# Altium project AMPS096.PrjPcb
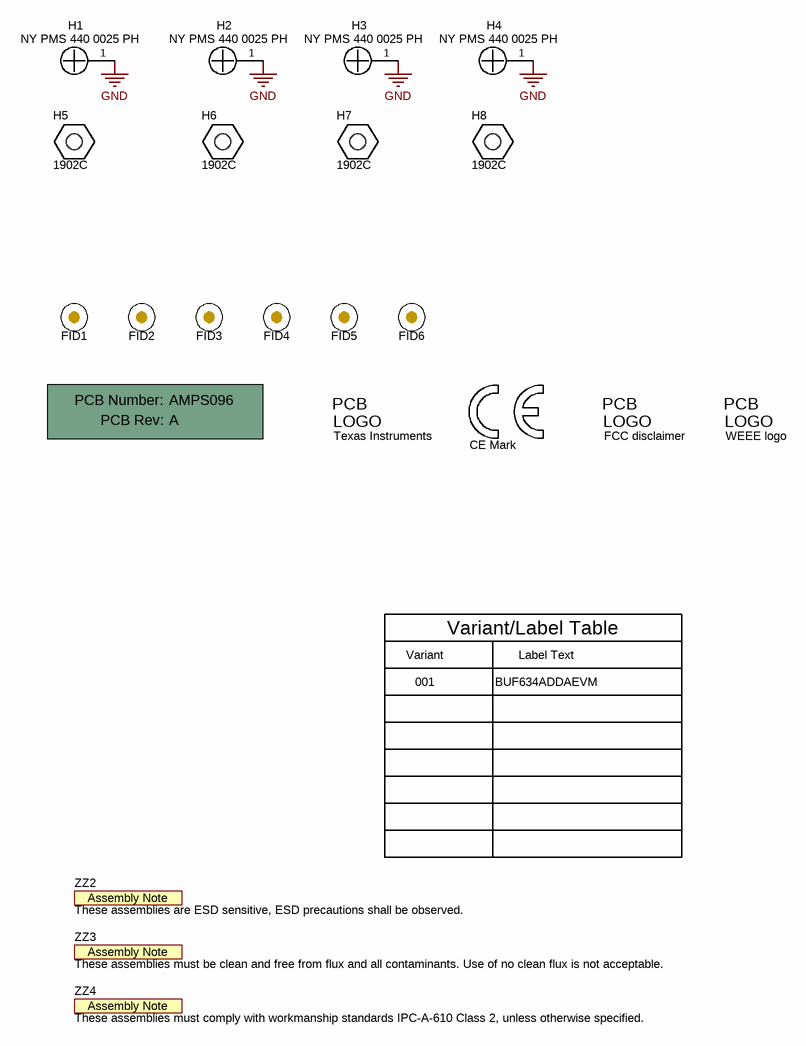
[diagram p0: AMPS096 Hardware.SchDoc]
TID: N/A; TechSupport: http://www.ti.com/support; SCH_Rev: A; Project Lead: Jacob Freet; PRJ_Title: BUF634ADDAEVM; PRJ_Number: AMPS096; PRJ_Engineer: Jacob Freet; PRJ_Customer: Public Release; PCB_Rev: A; PCB_Layout: Dennis Goeke; CopyrightYear: 2018
2 sheets, 83 parts. Net scope: global (net labels, ports and power ports of the same name join across sheets).
Board file: AMPS096.PcbDoc
Sheets:
  AMPS096 Hardware.SchDoc
  AMPS096.SchDoc

## Sheet AMPS096 Hardware.SchDoc
size 431 x 279 mm; Date: Not shown in title block; ApprovedBy: Not shown in title block; CheckedBy: Not shown in title block; Author: Not shown in title block; CompanyName: Not shown in title block; Engineer: Not shown in title block; Organization: Not shown in title block; Address1: Not shown in title block; Address2: Not shown in title block; Address3: Not shown in title block; Address4: Not shown in title block; DocumentNumber: 2; Revision: Use project parameter SCH_Rev; SheetNumber: 2; SheetTotal: 2; PageSetup: Record=PageOptions¦CenterHorizontal=True¦CenterVertical=True¦PrintScale=1.00¦XCorrection=1.00¦YCorrection=1.00¦PrintKind=0¦BorderSize=5000000¦LeftOffset=0¦BottomOffset=0¦Orientation=2¦PaperLength=1000¦PaperWidth=1000¦Scale=100¦PaperSource=15¦PrintQuality=600¦MediaType=1¦DitherType=10¦PaperKind=Letter¦PrintScaleMode=1

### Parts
!PCB  Printed Circuit Board  (value not drawn)  (mechanical)
FID1  Fiducial  [Fiducial10-20]  (value not drawn)
FID2  Fiducial  [Fiducial10-20]  (value not drawn)
FID3  Fiducial  [Fiducial10-20]  (value not drawn)
FID4  Fiducial  [Fiducial10-20]  (value not drawn)
FID5  Fiducial  [Fiducial10-20]  (value not drawn)
FID6  Fiducial  [Fiducial10-20]  (value not drawn)
H1  NY PMS 440 0025 PH  [NY PMS 440 0025 PH]
H2  NY PMS 440 0025 PH  [NY PMS 440 0025 PH]
H3  NY PMS 440 0025 PH  [NY PMS 440 0025 PH]
H4  NY PMS 440 0025 PH  [NY PMS 440 0025 PH]
H5  1902C  [Keystone_1902C]
H6  1902C  [Keystone_1902C]
H7  1902C  [Keystone_1902C]
H8  1902C  [Keystone_1902C]
Logo1  Texas Instruments  [TI_Stacked_Overlay_Small]  (no BOM)
Logo2  CE Mark  [CE_Mark_5mm]  (no BOM)
Logo3  FCC disclaimer  [FCC_disclaimer]  (no BOM)
Logo4  WEEE logo  [WEEE_Minimum]  (no BOM)
ZZ2  These assemblies are ESD sensitive, ESD precautions shall be observed.  [AssemblyNote]  (no BOM)
ZZ3  These assemblies must be clean and free from flux and all contaminants. Use of no clean flux is not acceptable.  [AssemblyNote]  (no BOM)
ZZ4  These assemblies must comply with workmanship standards IPC-A-610 Class 2, unless otherwise specified.  [AssemblyNote]  (no BOM)

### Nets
GND: H1.1 H2.1 H3.1 H4.1

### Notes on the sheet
- Variant
- Variant/Label Table
- Label Text
- 001
- BUF634ADDAEVM

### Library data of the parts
!PCB = CMP-0003618-2: Manufacturer: Any; PartNumber: AMPS096; CompType: PCB
FID1-FID6 = CMP-0077181-1: Fiducial mark.  There is nothing to buy or mount.
H1-H4 = CMP-0003617-1: Machine Screw, Round, #4-40 x 1/4, Nylon, Philips panhead; Manufacturer: B&F Fastener Supply; CompType: Hardware
H5-H8 = CMP-0003610-1: Standoff, Hex, 0.5"L #4-40 Nylon; Manufacturer: Keystone; CompType: Hardware
Logo1 = CMP-0074838-1: Texas Instrument Corporate Signature; SymbolCreator: a0412235; Lib Reference: TI_Logo; Library Reference: Logo
Logo2 = CMP-0074844-1: SymbolCreator: a0412235
Logo3 = CMP-0074847-1: FCC_disclaimer; Library Reference: Logo
Logo4 = CMP-0074769-1
ZZ2 = CMP-0077236-1
ZZ3 = CMP-0077237-1
ZZ4 = CMP-0077238-1

## Sheet AMPS096.SchDoc: BUF634ADDAEVM SCH
size 431 x 279 mm; Date: Not shown in title block; ApprovedBy: Not shown in title block; CheckedBy: Not shown in title block; Author: Not shown in title block; CompanyName: Not shown in title block; DrawnBy: Dennis Goeke; Engineer: Not shown in title block; Organization: Not shown in title block; Address1: Not shown in title block; Address2: Not shown in title block; Address3: Not shown in title block; Address4: Not shown in title block; DocumentNumber: 1; Revision: Use project parameter SCH_Rev; SheetNumber: 1; SheetTotal: 2; PageSetup: Record=PageOptions¦CenterHorizontal=True¦CenterVertical=True¦PrintScale=1.00¦XCorrection=1.00¦YCorrection=1.00¦PrintKind=0¦BorderSize=5000000¦LeftOffset=0¦BottomOffset=0¦Orientation=2¦PaperLength=1000¦PaperWidth=1000¦Scale=100¦PaperSource=15¦PrintQuality=600¦MediaType=1¦DitherType=10¦PaperKind=Letter¦PrintScaleMode=1
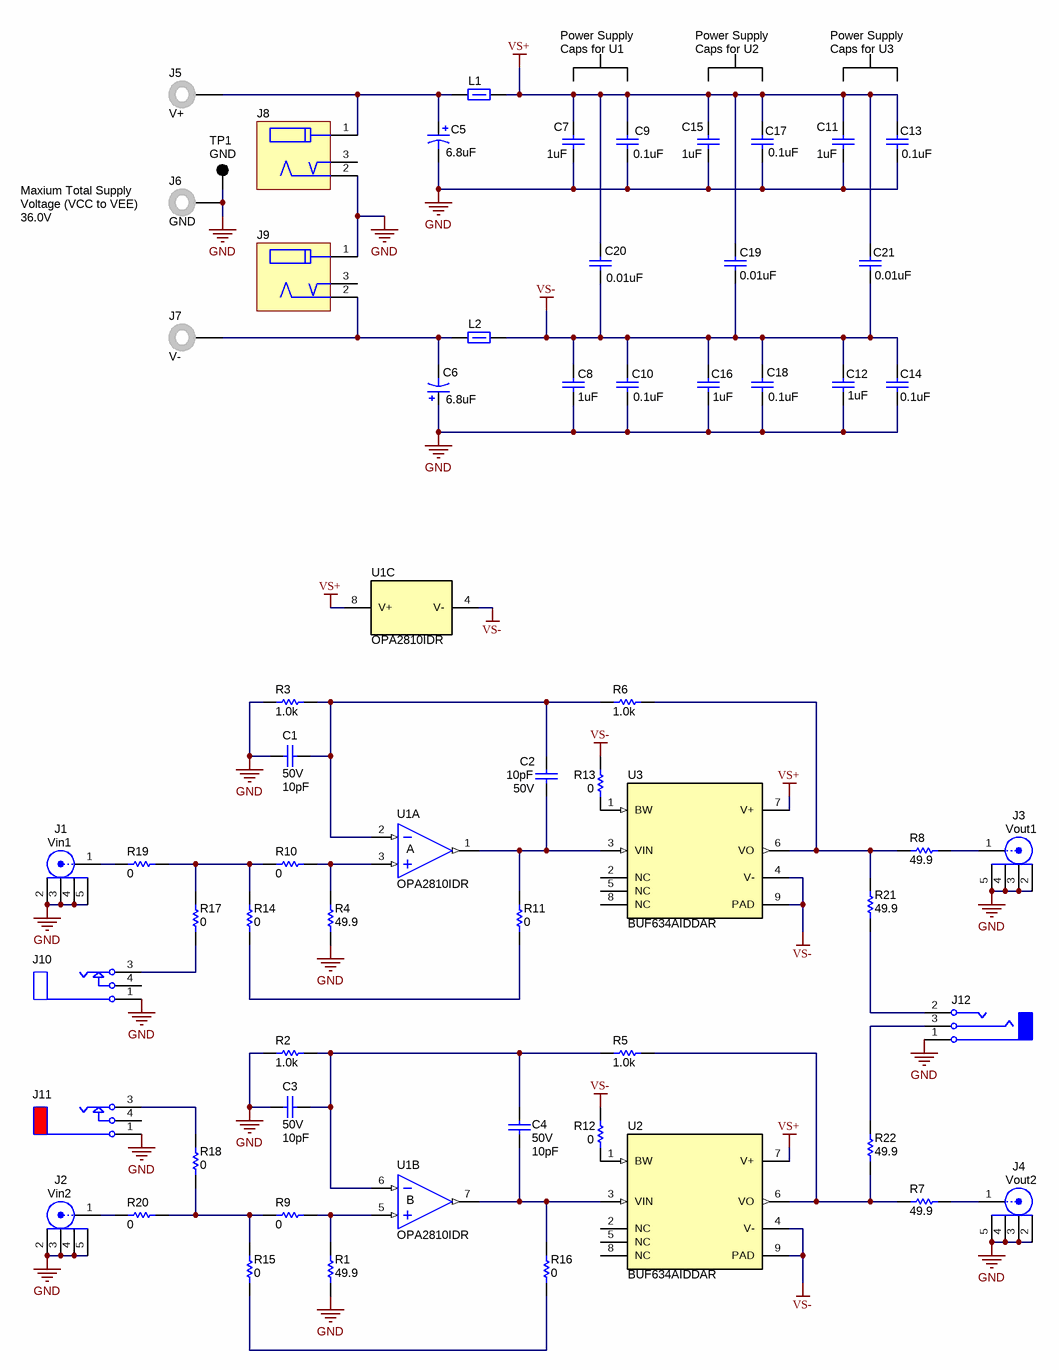
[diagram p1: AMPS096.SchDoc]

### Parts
C1  VDC_V: 50V  ValueDisplayed: 10pF  [0603L]  (hidden comment: C0603C100F5GAC7867)
C2  VDC_V: 50V  ValueDisplayed: 10pF  [0603L]  (hidden comment: C0603C100F5GAC7867)
C3  VDC_V: 50V  ValueDisplayed: 10pF  [0603L]  (hidden comment: C0603C100F5GAC7867)
C4  VDC_V: 50V  ValueDisplayed: 10pF  [0603L]  (hidden comment: C0603C100F5GAC7867)
C5  ValueDisplayed: 6.8uF  [7343-31]  (hidden comment: T495D685K050ATE300)
C6  ValueDisplayed: 6.8uF  [7343-31]  (hidden comment: T495D685K050ATE300)
C7  ValueDisplayed: 1uF  [0805L]  (hidden comment: 08055C105KAT2A)
C8  ValueDisplayed: 1uF  [0805L]  (hidden comment: 08055C105KAT2A)
C9  ValueDisplayed: 0.1uF  [0603]  (hidden comment: C1608X5R1H104K080AA)
C10  ValueDisplayed: 0.1uF  [0603]  (hidden comment: C1608X5R1H104K080AA)
C11  ValueDisplayed: 1uF  [0805L]  (hidden comment: 08055C105KAT2A)
C12  ValueDisplayed: 1uF  [0805L]  (hidden comment: 08055C105KAT2A)
C13  ValueDisplayed: 0.1uF  [0603]  (hidden comment: C1608X5R1H104K080AA)
C14  ValueDisplayed: 0.1uF  [0603]  (hidden comment: C1608X5R1H104K080AA)
C15  ValueDisplayed: 1uF  [0805L]  (hidden comment: 08055C105KAT2A)
C16  ValueDisplayed: 1uF  [0805L]  (hidden comment: 08055C105KAT2A)
C17  ValueDisplayed: 0.1uF  [0603]  (hidden comment: C1608X5R1H104K080AA)
C18  ValueDisplayed: 0.1uF  [0603]  (hidden comment: C1608X5R1H104K080AA)
C19  ValueDisplayed: 0.01uF  [0603L]  (hidden comment: 06031C103KAT2A)
C20  ValueDisplayed: 0.01uF  [0603L]  (hidden comment: 06031C103KAT2A)
C21  ValueDisplayed: 0.01uF  [0603L]  (hidden comment: 06031C103KAT2A)
J1  Vin1  [Johnson_142-0701-801_NoVias]
J2  Vin2  [Johnson_142-0701-801_NoVias]
J3  Vout1  [Johnson_142-0701-801_NoVias]
J4  Vout2  [Johnson_142-0701-801_NoVias]
J5  V+  [Keystone_6095]
J6  GND  [Keystone_6095]
J7  V-  [Keystone_6095]
J8  EJ508A  [Memory_EJ508A]  (value not drawn)
J9  EJ508A  [Memory_EJ508A]  (value not drawn)
J10  970  [Keystone_970]  (value not drawn)
J11  971  [Keystone_971]  (value not drawn)
J12  SJ-3523-SMT  [CUI_SJ-3523-SMT]  (value not drawn)
L1  HI1206N800R-10  [1206]  (value not drawn)
L2  HI1206N800R-10  [1206]  (value not drawn)
R1  ValueDisplayed: 49.9  [0603L]  (hidden comment: CRCW060349R9FKEA)
R2  ValueDisplayed: 1.0k  [0603L]  (hidden comment: CRCW06031K00JNEA)
R3  ValueDisplayed: 1.0k  [0603L]  (hidden comment: CRCW06031K00JNEA)
R4  ValueDisplayed: 49.9  [0603L]  (hidden comment: CRCW060349R9FKEA)
R5  ValueDisplayed: 1.0k  [0603L]  (hidden comment: CRCW06031K00JNEA)
R6  ValueDisplayed: 1.0k  [0603L]  (hidden comment: CRCW06031K00JNEA)
R7  ValueDisplayed: 49.9  [0603L]  (hidden comment: CRCW060349R9FKEA)
R8  ValueDisplayed: 49.9  [0603L]  (hidden comment: CRCW060349R9FKEA)
R9  ValueDisplayed: 0  [0603L]  (hidden comment: CRCW06030000Z0EA)
R10  ValueDisplayed: 0  [0603L]  (hidden comment: CRCW06030000Z0EA)
R11  ValueDisplayed: 0  [0603L]  (hidden comment: CRCW06030000Z0EA)
R12  ValueDisplayed: 0  [0603L]  (hidden comment: CRCW06030000Z0EA)
R13  ValueDisplayed: 0  [0603L]  (hidden comment: CRCW06030000Z0EA)
R14  ValueDisplayed: 0  [0603L]  (hidden comment: CRCW06030000Z0EA)
R15  ValueDisplayed: 0  [0603L]  (hidden comment: CRCW06030000Z0EA)
R16  ValueDisplayed: 0  [0603L]  (hidden comment: CRCW06030000Z0EA)
R17  ValueDisplayed: 0  [0603L]  (hidden comment: CRCW06030000Z0EA)
R18  ValueDisplayed: 0  [0603L]  (hidden comment: CRCW06030000Z0EA)
R19  ValueDisplayed: 0  [0603L]  (hidden comment: CRCW06030000Z0EA)
R20  ValueDisplayed: 0  [0603L]  (hidden comment: CRCW06030000Z0EA)
R21  ValueDisplayed: 49.9  [0603L]  (hidden comment: CRCW060349R9FKEA)
R22  ValueDisplayed: 49.9  [0603L]  (hidden comment: CRCW060349R9FKEA)
TP1  GND  [Keystone5001]
U1  OPA2810IDR  [D0008A_N]  (parts A,B,C of 3)
U2  BUF634AIDDAR  [DDA0008B_N]
U3  BUF634AIDDAR  [DDA0008B_N]

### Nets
GND: C1.2 C3.2 C5.2(-) C6.1(+) C7.2 C8.2 C9.2 C10.2 C11.2 C12.2 C13.2 C14.2 C15.2 C16.2 C17.2 C18.2 J1.2 J1.3 J1.4 J1.5 J2.2 J2.3 J2.4 J2.5 J3.2 J3.3 J3.4 J3.5 J4.2 J4.3 J4.4 J4.5 J6.1 J8.2 J9.1 J10.1(SLEEVE) J11.1(SLEEVE) J12.1(SLEEVE) R1.1 R2.1 R3.1 R4.2 TP1.1
VS+: C7.1 C9.1 C11.1 C13.1 C15.1 C17.1 C19.1 C20.1 C21.1 L1.2 U1.8(V+) U2.7(V+) U3.7(V+)
VS-: C8.1 C10.1 C12.1 C14.1 C16.1 C18.1 C19.2 C20.2 C21.2 L2.2 R12.1 R13.1 U1.4(V-) U2.4(V-) U2.9(PAD) U3.4(V-) U3.9(PAD)
NetC1_1: C1.1 C2.1 R3.2 R6.1 U1.2(IN-)
NetC2_2: C2.2 R11.2 U1.1(OUT) U3.3(VIN)
NetC3_1: C3.1 C4.1 R2.2 R5.1 U1.6(IN-)
NetC4_2: C4.2 R16.2 U1.7(OUT) U2.3(VIN)
NetC5_1: C5.1(+) J5.1 J8.1 L1.1
NetC6_2: C6.2(-) J7.1 J9.2 L2.1
NetJ1_1: J1.1 R19.2
NetJ2_1: J2.1 R20.2
NetJ3_1: J3.1 R8.1
NetJ4_1: J4.1 R7.1
NetJ10_3: J10.3(TIP) R17.1
NetJ11_3: J11.3(TIP) R18.2
NetJ12_2: J12.2(TIP) R21.2
NetJ12_3: J12.3(RING) R22.1
NetR1_2: R1.2 R9.1 U1.5(IN+)
NetR4_1: R4.1 R10.1 U1.3(IN+)
NetR5_2: R5.2 R7.2 R22.2 U2.6(VO)
NetR6_2: R6.2 R8.2 R21.1 U3.6(VO)
NetR9_2: R9.2 R15.2 R18.1 R20.1
NetR10_2: R10.2 R14.2 R17.2 R19.1
NetR11_1: R11.1 R14.1
NetR12_2: R12.2 U2.1(BW)
NetR13_2: R13.2 U3.1(BW)
NetR15_1: R15.1 R16.1

Not connected (* = marked no-connect by the designer): J8 3; J9 3; J10 4(TIP_SWITCH); J11 4(TIP_SWITCH); U2 2(NC) 5(NC) 8(NC); U3 2(NC) 5(NC) 8(NC)

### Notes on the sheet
- Power Supply
  Caps for U1
- Power Supply
  Caps for U2
- Power Supply
  Caps for U3
- Maxium Total Supply
  Voltage (VCC to VEE)
  36.0V

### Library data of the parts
C1-C4 = CMP-0006838-4: CAP, CERM, 10 pF, 50 V, +/- 1%, C0G/NP0, 0603; Manufacturer: Kemet; TaMin_C: -55°C; Polarized: N; SizeAreaWB_mm2: 4.68; Value1: Unknown; U/M: EA; Value: 10pF; TaMax_C: 125°C; SizeZ_mm: 1; SizeX_mm: 1.6; SizeY_mm: 0.8; Cap_Case: 0603; SizeArea_mm2: 1.28; CompType: Capacitor; AEC Category: Q200
C5 C6 = CMP-0011788-2: CAP, TA, 6.8 uF, 50 V, +/- 10%, 0.3 ohm, SMD; Manufacturer: Kemet; TaMin_C: -55°C; ESR_ohm: 3d; Polarized: Y; SizeAreaWB_mm2: 58.59; Value1: 0.3 ohm; U/M: EA; Value: 6.8uF; TaMax_C: 125°C; SizeZ_mm: 3.1; SizeX_mm: 7.3; SizeY_mm: 4.3; Cap_Case: D; Value2: 50V; SizeArea_mm2: 31.39; CompType: Capacitor; Cap_F: 6.8µF; IRMS_A: 6dA; AEC Category: Q200
C7 C8 C11 C12 C15 C16 = CMP-0007634-2: CAP, CERM, 1 uF, 50 V, +/- 10%, X7R, 0805; Manufacturer: AVX; TaMin_C: -55°C; Polarized: N; SizeAreaWB_mm2: 6.75; Value1: Unknown; U/M: EA; Value: 1uF; TaMax_C: 125°C; SizeZ_mm: 1.45; SizeX_mm: 2; SizeY_mm: 1.25; Cap_Case: 0805; Value2: 50V; SizeArea_mm2: 2.5; Cap_F: 1µF; AEC Category: Q200
C9 C10 C13 C14 C17 C18 = CMP-0007010-3: CAP, CERM, 0.1 uF, 50 V, +/- 10%, X5R, 0603; Manufacturer: TDK; TaMin_C: -55°C; ESR_ohm: 0.0296; Polarized: N; SizeAreaWB_mm2: 4.68; Value1: 0.0296 ohm; U/M: EA; Value: 0.1uF; TaMax_C: 85°C; SizeZ_mm: 1; SizeX_mm: 1.6; SizeY_mm: 0.8; Value2: 50V; SizeArea_mm2: 1.28; Cap_F: 100nF; IRMS_A: 971.99mA; AEC Category: Q200
C19-C21 = CMP-0006727-4: CAP, CERM, 0.01 uF, 100 V, +/- 10%, X7R, 0603; Manufacturer: AVX; TaMin_C: -55°C; ESR_ohm: 0.098; Polarized: N; SizeAreaWB_mm2: 4.68; Value1: 0.098 ohm; U/M: EA; Value: 0.01uF; TaMax_C: 125°C; SizeZ_mm: 1; SizeX_mm: 1.6; SizeY_mm: 0.8; Cap_Case: 0603; Value2: 100V; SizeArea_mm2: 1.28; CompType: Capacitor; Cap_F: 10nF; AEC Category: Q200
J1-J4 = CMP-0055828-1: Connector, End launch SMA, 50 ohm, SMT; Manufacturer: Cinch Connectivity; PartNumber: 142-0701-801; CNHeader: FALSE; Green_Lifecycle: Not Set; Green_REACh: Incomplete; CT: TRUE
J5-J7 = CMP-0055169-2: Standard Banana Jack, Uninsulated; Manufacturer: Keystone; PartNumber: 6095; CT: TRUE; Green_REACh: Passed; CNHeader: FALSE; Green_Lifecycle: Active
J8 J9 = CMP-0055800-1: Power Jack, 2.1x5.5mm, R/A, TH; Manufacturer: Memory Protection Devices; CNHeader: FALSE; Current_A: 5A; Gender: Male; Voltage_V: 12V
J10 = CMP-0055175-2: RCA Jack, White, R/A, TH; Manufacturer: Keystone; CNHeader: FALSE; Green_Lifecycle: Active; Green_REACh: Passed; CompType: Audio Connector; CT: TRUE
J11 = CMP-0055174-2: RCA Jack, Red, R/A, TH; Manufacturer: Keystone; CNHeader: FALSE; Green_Lifecycle: Active; Green_REACh: Passed; CompType: Audio Connector; CT: TRUE
J12 = CMP-0074907-1: Audio Jack, 3.5mm, Stereo, R/A, SMT; Manufacturer: CUI Inc.; CT: True; Green_REACh: Incomplete; CompType: Audio Connector; CNHeader: False; Green_Lifecycle: Not Set
L1 L2 = CMP-0003379-1: Ferrite Bead, 80 ohm @ 100 MHz, 3 A, 1206; Manufacturer: Laird-Signal Integrity Products; Ztyp@1GHz_Ohm: 129; ZTyp@100MHz_Ohm: 80; SizeAreaWB_mm2: 10.92; DCR_ohm: 0.035; Value1: 0.035 ohm; Value: 80 ohm; Imax_A: 3A; SizeZ_mm: 1.35; SizeX_mm: 3.2; SizeY_mm: 1.6; SizeArea_mm2: 5.12
R1 R4 = CMP-0022448-4: RES, 49.9, 1%, 0.1 W, AEC-Q200 Grade 0, 0603; Manufacturer: Vishay-Dale; Power_W: 100mW; TempCo: 100 ppm/C; Value_Code: 49R9; Value: 49.9; EIA_Code: E96; SizeX_mm: 1.6; SizeY_mm: 0.8; SizeZ_mm: 1; Value2: 0.1W; SizeArea_mm2: 1.28; AEC Qualified: Y; VDC_V: 75V; AEC Category: Q200; AEC Grade: 0
R2 R3 R5 R6 = CMP-0025729-4: RES, 1.0 k, 5%, 0.1 W, AEC-Q200 Grade 0, 0603; Manufacturer: Vishay-Dale; Power_W: 100mW; TempCo: 200 ppm/C; Value_Code: 1k00; Value: 1.0k; EIA_Code: E24; Res_ohm: 1k; SizeX_mm: 1.6; SizeY_mm: 0.8; SizeZ_mm: 1; Value2: 0.1W; SizeArea_mm2: 1.28; AEC Qualified: Y; VDC_V: 75V; AEC Category: Q200; AEC Grade: 0
R7 R8 R21 R22 = CMP-0022448-4: RES, 49.9, 1%, 0.1 W, AEC-Q200 Grade 0, 0603; Manufacturer: Vishay-Dale; Power_W: 100mW; TempCo: 100 ppm/C; Value_Code: 49R9; Value: 49.9; EIA_Code: E96; SizeX_mm: 1.6; SizeY_mm: 0.8; SizeZ_mm: 1; Value2: 0.1W; SizeArea_mm2: 1.28; CompType: Resistor; AEC Qualified: Y; VDC_V: 75V; AEC Category: Q200; AEC Grade: 0
R9-R20 = CMP-0025697-4: RES, 0, 5%, 0.1 W, AEC-Q200 Grade 0, 0603; Manufacturer: Vishay-Dale; Power_W: 100mW; TempCo: 200 ppm/C; Value_Code: 0000; Value: 0; EIA_Code: E24; SizeX_mm: 1.6; SizeY_mm: 0.8; SizeZ_mm: 1; Value2: 0.1W; SizeArea_mm2: 1.28; CompType: Resistor; AEC Qualified: Y; VDC_V: 75V; AEC Category: Q200
TP1 = CMP-0055138-1: Test Point, Miniature, Black, TH; Manufacturer: Keystone; CNHeader: FALSE; Green_Lifecycle: Active; Green_REACh: Passed; ContactFinish: Silver; CT: TRUE
U1 = CMP-0085273-1: High Performance Low Cost Rail-to-Rail Input/Output HV FET Op Amps, D0008A (SOIC-8); Manufacturer: Texas Instruments; Alternate PartNumber: OPA2810IDT; Alternate Manufacturer: None; SizeAreaWB_mm2: 56.58; SizeZ_mm: 1.75; AEC Qualified: N; CompType: IC; Rating: Catalog; SizeY_mm: 6.2; SizeArea_mm2: 30.38; SizeX_mm: 4.9; AEC Category: Q200
U2 U3 = CMP-0861073-1: 36-V, 210-MHz, 250-mA Output, High-Speed Buffer, DDA0008B (HSOIC-8); Manufacturer: Texas Instruments; Alternate PartNumber: BUF634AIDDAT; Alternate Manufacturer: None; Rating: Catalog; SizeArea_mm2: 29.4; AEC Category: Q200; SizeZ_mm: 1.7; AEC Qualified: N; CompType: IC; SizeY_mm: 4.9; SizeX_mm: 6; SizeAreaWB_mm2: 55.2

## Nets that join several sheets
GND: AMPS096 Hardware (H1.1 H2.1 H3.1 H4.1), AMPS096 (43 pins)

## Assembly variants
001: not fitted C1 C2 C3 C4 C7 C8 C9 C10 C20 FID1 FID2 FID3 R1 R2 R3 R4 R5 R6 R9 R10 R17 R18 R21 R22 U1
